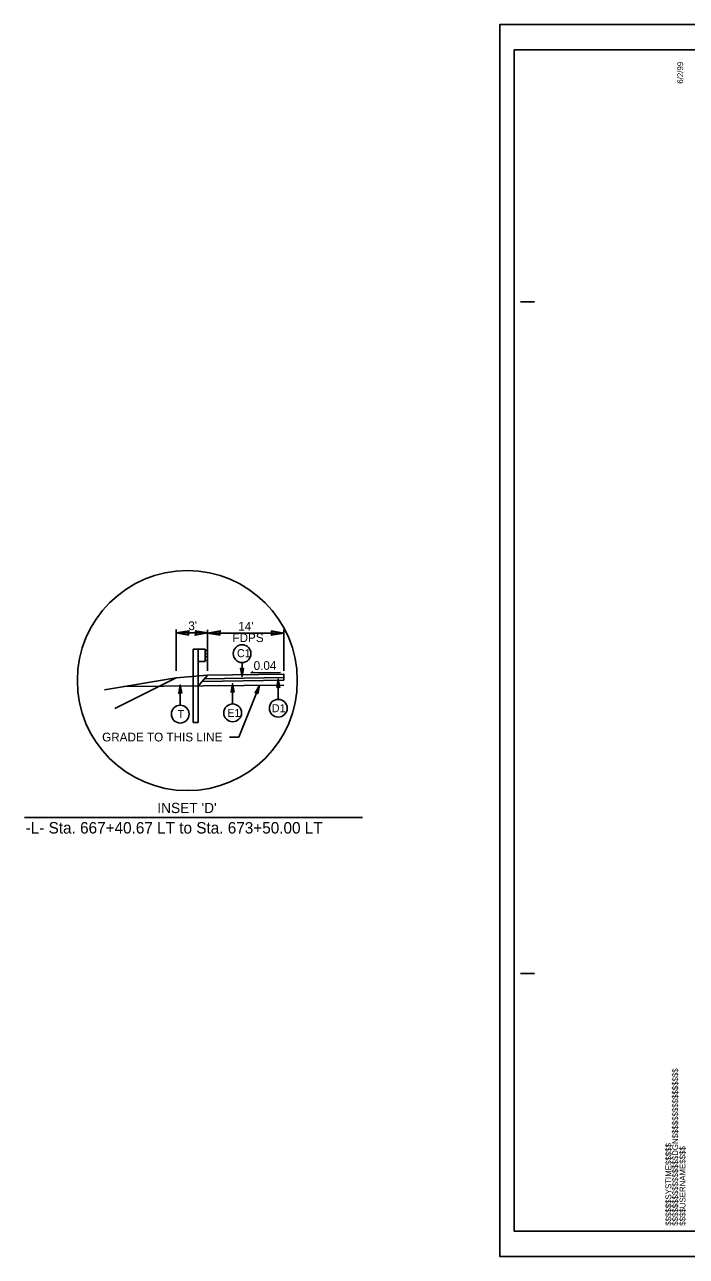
# Model space of a CAD drawing. Extents: x 2294370 to 2294957, y 719276 to 719941.
# Drawn here: x 2294370.3 to 2294488.5, y 719276.3 to 719496.3 of the extents above; entities that cross this region are included whole.
import ezdxf

# ---------------------------------------------------------------- set-up
doc = ezdxf.new("R2010")
doc.units = 0
for name, color, linetype in [('Default', 7, 'Continuous'), ('Old_Level_1', 7, 'Continuous'), ('Old_Level_11', 7, 'Continuous'), ('Prop CMT Guardrail Graphics', 7, 'Continuous'), ('Sheet Cutting Line CELL', 7, 'Continuous'), ('Sheet Plot Border Inside CELL', 7, 'Continuous'), ('Sheet Plot Border Outside CELL', 7, 'Continuous'), ('Sheet Typical CELL', 7, 'Continuous'), ('Typical Hinge Slope Arterial CELL', 7, 'Continuous')]:
    doc.layers.add(name, color=color, linetype=linetype)

msp = doc.modelspace()

# ---------------------------------------------------------------- linework, layer by layer
at = {"layer": 'Default'}
for p, q in [((2294409.13, 719379.89), (2294409.13, 719382.4)), ((2294398.09, 719374.78), (2294398.09, 719378.4)), ((2294402.98, 719380.12), (2294402.98, 719380.12)), ((2294407.45, 719375), (2294407.45, 719378.62)), ((2294408.53, 719369.1), (2294412.23, 719378.3)), ((2294415.6, 719375.83), (2294415.6, 719379.45)), ((2294406.86, 719369.1), (2294408.53, 719369.1))]:
    msp.add_line(p, q, dxfattribs=at)
for points in [[(2294416.57, 719379.75), (2294416.57, 719379.75), (2294416.57, 719380.34), (2294402.98, 719380.12)], [(2294402.98, 719380.12), (2294402.98, 719380.12), (2294402.45, 719379.52)], [(2294402.45, 719379.52), (2294416.57, 719379.75)]]:
    msp.add_lwpolyline(points, dxfattribs=at)
for points in [[(2294409.38, 719381.38), (2294409.13, 719379.89), (2294408.86, 719381.39), (2294409.13, 719381.2)], [(2294398.35, 719376.91), (2294398.09, 719378.4), (2294397.83, 719376.9), (2294398.09, 719377.09)], [(2294407.7, 719377.13), (2294407.45, 719378.62), (2294407.18, 719377.12), (2294407.45, 719377.31)], [(2294411.93, 719376.82), (2294412.25, 719378.3), (2294411.44, 719377.01), (2294411.76, 719377.09)], [(2294415.35, 719377.96), (2294415.6, 719379.45), (2294415.87, 719377.95), (2294415.6, 719378.14)]]:
    msp.add_lwpolyline(points, close=True, dxfattribs=at)
for centre in [(2294409.13, 719383.99), (2294415.6, 719374.24), (2294398.09, 719373.19), (2294407.45, 719373.41)]:
    msp.add_circle(centre, 1.59, dxfattribs=at)
at = {"layer": 'Old_Level_1'}
for p, q in [((2294416.57, 719380.34), (2294402.98, 719380.12)), ((2294410.71, 719380.54), (2294411.13, 719380.75)), ((2294415.97, 719380.62), (2294410.71, 719380.54)), ((2294387.99, 719378.11), (2294416.58, 719378.34)), ((2294402.98, 719380.12), (2294397.38, 719379.67)), ((2294402.98, 719380.12), (2294401.29, 719378.21)), ((2294402.45, 719379.52), (2294402, 719379.02)), ((2294416.57, 719379.25), (2294402, 719379.02)), ((2294402, 719379.02), (2294416.57, 719379.25)), ((2294416.57, 719379.75), (2294402.45, 719379.52)), ((2294416.57, 719379.75), (2294402.45, 719379.52)), ((2294416.57, 719379.25), (2294416.57, 719379.75)), ((2294416.57, 719379.25), (2294416.57, 719379.25))]:
    msp.add_line(p, q, dxfattribs=at)
at = {"layer": 'Old_Level_11'}
for p, q in [((2294397.38, 719380.9), (2294397.38, 719388.28)), ((2294402.98, 719387.68), (2294397.38, 719387.68)), ((2294402.98, 719380.9), (2294402.98, 719388.27)), ((2294416.57, 719387.67), (2294402.98, 719387.67)), ((2294416.57, 719380.9), (2294416.57, 719388.27)), ((2294430.64, 719354.74), (2294370.28, 719354.74))]:
    msp.add_line(p, q, dxfattribs=at)
for points in [[(2294399.63, 719387.29), (2294397.38, 719387.68), (2294399.65, 719388.08), (2294399.36, 719387.68)], [(2294400.76, 719388.06), (2294403.01, 719387.68), (2294400.75, 719387.28), (2294401.03, 719387.68)], [(2294405.23, 719387.28), (2294402.98, 719387.67), (2294405.25, 719388.07), (2294404.96, 719387.67)], [(2294414.35, 719388.05), (2294416.6, 719387.67), (2294414.34, 719387.27), (2294414.62, 719387.67)]]:
    msp.add_lwpolyline(points, close=True, dxfattribs=at)
msp.add_circle((2294399.35, 719379.18), 19.65, dxfattribs=at)
at = {"layer": 'Prop CMT Guardrail Graphics'}
for p, q in [((2294400.38, 719380.14), (2294400.38, 719384.81)), ((2294400.38, 719384.81), (2294401.29, 719384.81)), ((2294400.38, 719380.14), (2294400.38, 719384.81)), ((2294400.38, 719384.81), (2294401.29, 719384.81)), ((2294400.38, 719380.14), (2294400.38, 719384.81)), ((2294400.38, 719384.81), (2294401.29, 719384.81)), ((2294401.29, 719384.81), (2294401.29, 719380.12)), ((2294401.29, 719382.6), (2294401.29, 719384.81)), ((2294401.29, 719384.81), (2294402.53, 719384.81)), ((2294401.29, 719384.81), (2294401.29, 719380.12)), ((2294401.29, 719382.6), (2294401.29, 719384.81)), ((2294401.29, 719384.81), (2294402.53, 719384.81)), ((2294401.29, 719382.6), (2294401.29, 719384.81)), ((2294401.29, 719384.81), (2294402.53, 719384.81)), ((2294401.29, 719384.81), (2294401.29, 719380.12)), ((2294402.53, 719384.81), (2294402.53, 719382.6)), ((2294402.53, 719384.81), (2294402.53, 719382.6)), ((2294402.53, 719384.81), (2294402.53, 719382.6)), ((2294402.53, 719384.66), (2294402.53, 719382.75)), ((2294402.72, 719384.62), (2294402.53, 719384.66)), ((2294402.98, 719384.43), (2294402.72, 719384.62)), ((2294402.53, 719382.6), (2294401.29, 719382.6)), ((2294402.53, 719382.6), (2294401.29, 719382.6)), ((2294402.53, 719382.6), (2294401.29, 719382.6)), ((2294402.53, 719382.75), (2294402.72, 719382.79)), ((2294402.56, 719383.79), (2294402.98, 719384.17)), ((2294402.56, 719383.62), (2294402.56, 719383.79)), ((2294402.98, 719383.25), (2294402.56, 719383.62)), ((2294402.72, 719382.79), (2294402.98, 719382.98)), ((2294402.98, 719384.17), (2294402.98, 719384.43)), ((2294402.98, 719382.98), (2294402.98, 719383.25)), ((2294400.38, 719371.72), (2294400.38, 719380.14)), ((2294400.38, 719371.72), (2294400.38, 719380.14)), ((2294400.38, 719371.72), (2294400.38, 719380.14)), ((2294401.29, 719380.12), (2294401.29, 719371.72)), ((2294401.29, 719380.12), (2294401.29, 719371.72)), ((2294401.29, 719380.12), (2294401.29, 719371.72)), ((2294401.29, 719371.72), (2294400.38, 719371.72)), ((2294401.29, 719371.72), (2294400.38, 719371.72)), ((2294401.29, 719371.72), (2294400.38, 719371.72))]:
    msp.add_line(p, q, dxfattribs=at)
at = {"layer": 'Sheet Cutting Line CELL'}
for p, q in [((2294791.96, 719496.34), (2294455.16, 719496.34)), ((2294455.16, 719496.34), (2294455.16, 719276.34)), ((2294455.16, 719276.34), (2294791.96, 719276.34))]:
    msp.add_line(p, q, dxfattribs=at)
at = {"layer": 'Sheet Plot Border Inside CELL'}
msp.add_lwpolyline([(2294791.06, 719491.85), (2294457.76, 719491.85), (2294457.76, 719280.83), (2294791.06, 719280.83)], close=True, dxfattribs=at)
at = {"layer": 'Sheet Plot Border Outside CELL'}
for points in [[(2294455.16, 719276.34), (2294791.96, 719276.34), (2294791.96, 719496.34), (2294455.16, 719496.34)], [(2294791.96, 719496.34), (2294455.16, 719496.34), (2294455.16, 719276.34), (2294791.96, 719276.34)]]:
    msp.add_lwpolyline(points, close=True, dxfattribs=at)
at = {"layer": 'Sheet Typical CELL'}
for p, q in [((2294458.86, 719446.84), (2294461.36, 719446.84)), ((2294458.86, 719326.84), (2294461.36, 719326.84))]:
    msp.add_line(p, q, dxfattribs=at)
at = {"layer": 'Typical Hinge Slope Arterial CELL'}
for p in [(2294384.57, 719377.54), (2294386.42, 719374.19)]:
    msp.add_line(p, (2294397.38, 719379.67), dxfattribs=at)

# ---------------------------------------------------------------- texts
at = {"layer": 'Default'}
for s, height, p in [('C1', 1.429, (2294408.22, 719383.36)), ('T', 1.43, (2294397.62, 719372.47)), ('E1', 1.429, (2294406.49, 719372.7)), ('D1', 1.429, (2294414.45, 719373.53))]:
    msp.add_text(s, height=height, rotation=359.9999, dxfattribs=at).set_placement(p)
at = {"layer": 'Old_Level_1'}
for s, height, rotation, p in [('0.04', 1.562, 0.4719, (2294411.2, 719381.07)), ("INSET 'D'", 1.833, 0, (2294393.98, 719355.51)), ('-L- Sta. 667+40.67 LT to Sta. 673+50.00 LT', 2.0454, 360, (2294370.46, 719351.86))]:
    msp.add_text(s, height=height, rotation=rotation, dxfattribs=at).set_placement(p)
at = {"layer": 'Old_Level_11'}
for s, height, rotation, p in [("3'", 1.562, 360, (2294399.53, 719388.19)), ("14'", 1.562, 360, (2294408.45, 719388.11)), ('FDPS', 1.562, 360, (2294407.41, 719386.06)), ('GRADE TO THIS LINE', 1.5625, 0, (2294384.13, 719368.31))]:
    msp.add_text(s, height=height, rotation=rotation, dxfattribs=at).set_placement(p)
at = {"layer": 'Sheet Typical CELL'}
for s, p in [('6/2/99', (2294487.93, 719485.79)), ('$$$$$$$$$$$$$$$$DGN$$$$$$$$$$$$$$$$', (2294487.03, 719281.81)), ('$$$$$$SYSTIME$$$$$', (2294485.82, 719281.81)), ('$$$$USERNAME$$$$', (2294488.34, 719281.81))]:
    msp.add_text(s, height=1.05, rotation=90, dxfattribs=at).set_placement(p)

doc.saveas('drawing.dxf')
